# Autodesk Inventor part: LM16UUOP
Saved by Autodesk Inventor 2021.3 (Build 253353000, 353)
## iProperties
Created: 2022-03
Part Number: LM16UUOP
Material: Generic
Document SubType Name: Modeling
Designer: Administrator
Density: 1 g/cm^3
Appearance: Default
Title: LM16UUOP
Author: Administrator
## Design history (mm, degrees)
feature "Body1"
feature "Body2"
feature "Body3"
feature "Body4"
feature "Body5"
body "Solid1"
body "Solid2"
body "Solid3"
body "Solid4"
body "Solid5"
